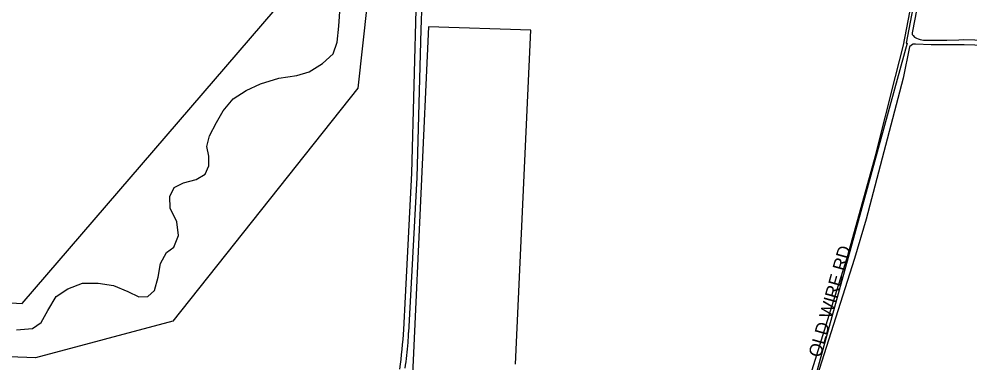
# Model space of a CAD drawing. Extents: x 0 to 712119, y 0 to 761125.
# Drawn here: x 686589 to 690289, y 717493 to 718831 of the extents above; entities that cross this region are included whole.
import ezdxf

# ---------------------------------------------------------------- set-up
doc = ezdxf.new("R2010")
doc.units = 0
for name, color, linetype in [('city boundary', 7, 'Continuous'), ('PAVED ROADS', 7, 'Continuous'), ('Priority 26', 7, 'Continuous'), ('stream or creek', 7, 'Continuous'), ('street names', 7, 'Continuous')]:
    doc.layers.add(name, color=color, linetype=linetype)

msp = doc.modelspace()

# ---------------------------------------------------------------- linework, layer by layer
at = {"layer": 'city boundary'}
for points in [[(690306.7, 720076), (690281.2, 719941.4), (690182.7, 719435.1), (690071.5, 718899.9), (690040.1, 718737.1), (690044.8, 718736.9), (689687.7, 717441.8)], [(688520.5, 717488.4), (688580, 718786.9), (688182.1, 718799.6), (688122.8, 717504.2), (688061.8, 716168.6)]]:
    msp.add_lwpolyline(points, dxfattribs=at)
at = {"layer": 'PAVED ROADS'}
for points in [[(690308.2, 720038.8), (690182.4, 719385.4), (690121.6, 719072.1), (690065, 718783.5), (690064, 718777), (690064.5, 718770.5), (690067.5, 718766), (690073, 718760.5), (690080.5, 718756.5), (690087, 718753), (690095.5, 718750.5), (690107.5, 718749), (690162.5, 718749), (690199.5, 718748), (690246, 718750), (690263, 718750.5), (690353, 718748)], [(688086, 717622.5), (688093, 717750), (688117.5, 718231.5), (688136, 718916.5), (688145.5, 719251.5), (688161.5, 719620.5), (688162, 719643), (688155, 719664)], [(689675.5, 717466.5), (689771, 717774.5), (689811.5, 717902), (689921, 718298.4), (689999.3, 718607.2), (690030.5, 718729.5), (690030.5, 718729.5), (690203.9, 719634.2), (690203.9, 719634.2)], [(688155.6, 718897.3), (688155.5, 718896), (688152.5, 718789.5), (688137.3, 718214.5), (688104.6, 717611.8)], [(690392.1, 718726.6), (690266.5, 718730.3), (690178.7, 718730.6), (690138.3, 718730), (690077.2, 718732.5), (690067.8, 718732.2), (690062, 718729.5), (690053.5, 718722.5), (690028.5, 718601), (689885, 718052), (689839, 717899.5), (689656.5, 717325)]]:
    msp.add_lwpolyline(points, dxfattribs=at)
for centre, radius, start, end in [((685099.6, 717835.7), 2994, 352.9561, 355.9175), ((686923.8, 717655.8), 1181.6, 355.9373, 357.8647), ((686923.8, 717655.8), 1181.6, 351.0756, 355.9373)]:
    msp.add_arc(centre, radius, start, end, dxfattribs=at)
at = {"layer": 'Priority 26'}
for points in [[(687906.9, 718562.2), (687187.1, 717656.1), (686652.3, 717513.3), (685689.9, 717549.4), (685432.2, 717770.3), (685296.4, 717781.5), (685246.2, 718282.5), (685153, 718305.4), (685192.8, 718513.9), (685454.9, 718451), (685511, 718043.1), (685734.3, 717776.6), (686601.4, 717724), (687769.1, 719083.2), (687791.4, 719283.3)], [(687980.3, 719221.9), (687906.9, 718562.2)]]:
    msp.add_lwpolyline(points, dxfattribs=at)
at = {"layer": 'stream or creek'}
msp.add_lwpolyline([(686578.4, 717622), (686641, 717626.7), (686675.3, 717650.1), (686700.3, 717697), (686733.1, 717751.7), (686778.4, 717781.3), (686836.3, 717803.2), (686897.2, 717803.2), (686956.6, 717793.8), (687012.8, 717770.4), (687055, 717750.1), (687089.4, 717751.7), (687115.9, 717775.1), (687130, 717826.7), (687139.4, 717879.8), (687162.8, 717922), (687190.9, 717943.8), (687209.7, 717989.2), (687203.4, 718042.3), (687176.9, 718095.4), (687175.3, 718140.7), (687192.5, 718175.1), (687228.4, 718193.9), (687278.4, 718206.3), (687312.8, 718226.7), (687326.9, 718259.4), (687326.9, 718297), (687319, 718334.5), (687330, 718376.6), (687356.6, 718428.2), (687383.1, 718473.5), (687422.2, 718520.4), (687472.2, 718553.2), (687528.5, 718578.2), (687600.3, 718600.1), (687669.1, 718611), (687717.5, 718625.1), (687769.1, 718657.9), (687811.2, 718695.4), (687826.9, 718740.7), (687833.1, 718803.2), (687837.8, 718878.2)], dxfattribs=at)

# ---------------------------------------------------------------- texts
at = {"layer": 'street names'}
msp.add_text('OLD WIRE RD.', height=50, rotation=74.4091, dxfattribs=at).set_placement((689707.5, 717511.5))

doc.saveas('drawing.dxf')
